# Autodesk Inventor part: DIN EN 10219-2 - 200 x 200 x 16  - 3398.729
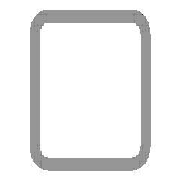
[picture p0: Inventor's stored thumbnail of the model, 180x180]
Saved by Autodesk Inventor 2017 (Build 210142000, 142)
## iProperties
IsCustomPart: 1
Created: 2017-11
Part Number: DIN EN 10219-2 - 200 x 200 x 16  - 3398.729
Material: Steel, Mild
Description: Cold formed welded structural hollow sections of non-alloy and fine grain structural steel
Document SubType Name: Modeling
Standard: DIN
Designer: iusti
Standard Revision: 2006-07
Standards Organization: DIN
Language: en-US
Size Designation: 200 x 200 x 16
Categories: <MemberInstance><Categories><Category DisplayName="Structural Shapes" InternalName="089c4875-fa83-4c05-b084-43b9cc11f5ed" Mnemonic="GRDR"><CategoryParameter Dis
Stock Number: 200 x 200 x 16
Density: 7.85 g/cm^3
Appearance: Semi-Polished
Mass: 260009 g
Surface Area: 41812.5 cm^2
Volume: 33122.1 cm^3
_CCFamilyMember: 103
_CCFamilyDisplayName: DIN EN 10219-2 (Square Hollow Section - Cold Formed) - Cold formed welded structural hollow sections of non-alloy and fine grain structural steel
_FrameMemberDoc: Frame Member File
_Version: 15.0.0
_GetPNFromCC: 1
G_L: 3398.729 mm
G_W: 200.000 mm
G_H: 200.000 mm
+C5A7F213-7B8F-416C-AD71-AED6F988D7A0+CUTDETAIL1: Cut
+92DA0260-704C-43BE-8B8B-0C986C6355A8+CUTDETAIL2: Cut
Author: iusti
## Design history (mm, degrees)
node "Start plane"
node "End plane"
sketch "Sketch"
  geometry: L1 (-100, -52)-(-100, 52); L2 (-52, 100)-(52, 100); L3 (100, 52)-(100, -52); L4 (52, -100)-(-52, -100); L5 (-52, 84)-(52, 84); L6 (84, 52)-(84, -52); L7 (52, -84)-(-52, -84); L8 (-84, -52)-(-84, 52); L9 (0, 153.918)-(0, -153.918) reference; L10 (-153.918, 0)-(153.918, 0) reference; A1 r 48 centre (-52, -52) between (-100, -52) and (-52, -100); A2 r 48 centre (-52, 52) between (-52, 100) and (-100, 52); A3 r 48 centre (52, 52) between (100, 52) and (52, 100); A4 r 48 centre (52, -52) between (52, -100) and (100, -52); A5 r 32 centre (-52, 52) between (-52, 84) and (-84, 52); A6 r 32 centre (52, 52) between (84, 52) and (52, 84); A7 r 32 centre (52, -52) between (52, -84) and (84, -52); A8 r 32 centre (-52, -52) between (-84, -52) and (-52, -84)
  constraints: 16 end point, 16 point on circle, 8 centre point, 8 tangent, 4 parallel, 3 equal radius, 2 perpendicular, 7 other
  dimensions: "d7" = 48 radius of A1 (= G_IR); "d10" = 200 distance between parallel lines of L2 L4 (= G_H); "d11" = 200 distance between parallel lines of L1 L3 (= G_W); "d12" = 16 distance between parallel lines of L3 L6 (= G_T); "d15" = 100 distance between parallel lines of L2 L10 (= 0.5 x d10); "d16" = 100 distance between parallel lines of L9 L3 (= 0.5 x d11)
extrude "Body" new body sketch "Sketch" stored distance "d3" = 3398.72851 (= G_L); taper "d4" = 0 deg
node "Driven Length"
  sketch "Sketch3"
    geometry: L1 (0, 0)-(10, 0) reference
    constraints: 2 end point, 1 horizontal
  workplane "Work Plane3"
  sketch "Sketch4"
    geometry: L1 (-2, 39.174)-(12, 39.174) reference; L2 (-2, 3437.902)-(12, 3437.902) reference
    dimensions: "d18" = 3398.72851 distance between parallel lines of L1 L2 (derived)
workplane "Work Plane4"
split "Split1"
workplane "Work Plane5"
split "Split2"
body "Solid1"
other parameters: "G_W" = 200 [user parameter; used in 1 equation term], "G_H" = 200 [user parameter; used in 1 equation term], "G_T" = 16 [user parameter; used in 1 equation term], "G_IR" = 48 [user parameter; used in 1 equation term], "G_L" = 3398.72851 (= d18) [user parameter; used in 1 equation term], "G_OFFSET_START" = -39.1736 [user parameter; used in 1 equation term], "G_OFFSET_END" = -18.71453 [user parameter; used in 1 equation term], "d13" = 39.1736 (= -G_OFFSET_START), "d14" = 3437.90211 (= G_OFFSET_END + B_L), "B_L" = 3456.61664 [user parameter; used in 1 equation term], "d17" = 90 deg
